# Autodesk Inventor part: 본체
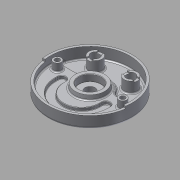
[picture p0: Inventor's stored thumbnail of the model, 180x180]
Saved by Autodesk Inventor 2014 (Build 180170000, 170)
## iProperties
Created: 2015-06
Part Number: 본체
Material: 알루미늄 6061
Document SubType Name: Modeling
Designer: MYHOME
Mass: 1070.49 g
Surface Area: 1035.62 cm^2
Volume: 395.014 cm^3
Density: 2.71 g/cm^3
Appearance: 알루미늄 - 평지
Author: MYHOME
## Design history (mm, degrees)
sketch "스케치1"
  geometry: C1 r 95 at (0, 0); 1 further point
  constraints: 1 centre point, 1 coincident
  dimensions: "d0" = 190 diameter of C1
extrude "돌출1" new body sketch "스케치1" distance "d1" = 32; taper "d2" = 0 deg
sketch "스케치3"
  geometry: L1 (-34.013, 24.639)-(-125.605, 24.639); L2 (34.013, 24.639)-(121.919, 24.639); C1 r 95 at (0, 0) reference; C2 r 90 at (0, 0); A1 r 42 centre (0, 0) between (-34.013, 24.639) and (34.013, 24.639)
  constraints: 4 end point, 2 centre point, 2 coincident, 2 point on circle, 1 collinear, 1 horizontal, 1 point on line
  dimensions: "d6" = 180 diameter of C2; "d125" = 84 diameter of A1; "d126" = 24.63947 distance from line of C1.centre L1
extrude "돌출3" cut sketch "스케치3" distance "d7" = 25; taper "d8" = 0 deg
sketch "스케치5"
  geometry: L1 (0, 0)-(-95, 0); L2 (0, 0)-(95, 0); L3 (0, 0)-(-94.075, -13.221); L4 (0, 0)-(94.075, -13.221); A1 r 95 centre (0, 0) between (-95, 0) and (95, 0) reference
  constraints: 8 end point, 4 point on circle, 1 collinear, 1 horizontal
  dimensions: "d12" = 8 deg angle of L3 L1; "d13" = 8 deg angle of L4 L2
extrude "돌출5" cut sketch "스케치5" distance "d14" = 5; taper "d15" = 0 deg
sketch "스케치11"
  geometry: L1 (-31.129, 16)-(-75.657, 16); L2 (31.129, 16)-(75.657, 16); A1 r 90 centre (0, 0) between (85.114, 29.25) and (-85.114, 29.25) reference; A2 r 35 centre (0, 0) between (31.129, 16) and (-31.129, 16); A3 r 10 centre (-75.657, 26) between (-85.114, 29.25) and (-75.657, 16); A4 r 10 centre (75.657, 26) between (75.657, 16) and (85.114, 29.25)
  constraints: 8 point on circle, 4 end point, 4 tangent, 3 centre point, 1 coincident, 1 collinear, 1 horizontal
  dimensions: "d36" = 70 diameter of A2; "d37" = 16 distance from line of A2.centre L1; "d38" = 16 distance from line of A1.centre L2; "d39" = 10 radius of A3; "d40" = 10 radius of A4
extrude "돌출13" join sketch "스케치11" distance "d56" = 7; taper "d57" = 0 deg
sketch "스케치14"
  geometry: C1 r 35 at (0, 0); A1 r 90 centre (0, 0) between (-85.114, 29.25) and (85.114, 29.25) reference
  constraints: 1 centre point, 1 coincident
  dimensions: "d58" = 70 diameter of C1
extrude "돌출14" join sketch "스케치14" distance "d59" = 10; taper "d60" = -10 deg
sketch "스케치15"
  geometry: L1 (75.657, 16)-(31.129, 16) reference; L2 (-50, -19)-(-50, -14); L3 (50, -19)-(50, -14); L4 (41, -14)-(41, -19); L5 (59, -14)-(59, -19); L6 (-59, -14)-(-59, -19); L7 (-41, -14)-(-41, -19); A1 r 35 centre (0, 0) between (-31.129, 16) and (31.129, 16) reference; A2 r 50 centre (0, -19) between (-50, -19) and (50, -19); A3 r 59 centre (0, -19) between (-59, -19) and (59, -19); A4 r 41 centre (0, -19) between (-41, -19) and (41, -19); A5 r 9 centre (-50, -19) between (-41, -19) and (-59, -19); A6 r 9 centre (50, -19) between (59, -19) and (41, -19); A7 r 9 centre (-50, -14) between (-59, -14) and (-41, -14); A8 r 9 centre (50, -14) between (41, -14) and (59, -14)
  constraints: 14 point on circle, 12 end point, 10 tangent, 7 centre point, 2 coincident, 2 horizontal alignment, 1 parallel, 1 perpendicular, 1 vertical alignment
  dimensions: "d61" = 19 distance of A1.centre A2.centre; "d62" = 41 radius of A4; "d63" = 59 radius of A3; "d85" = 5 distance of L2.start L2.end; "d86" = 5 distance of L3.start L3.end; "d87" = 18 diameter of A7; "d88" = 18 diameter of A8
sketch "스케치16"
  geometry: C1 r 15 at (-40, 52); C2 r 15 at (40, 52); A1 r 35 centre (0, 0) between (31.129, 16) and (-31.129, 16) reference
  constraints: 2 centre point, 1 horizontal alignment
  dimensions: "d64" = 30 diameter of C1; "d65" = 30 diameter of C2; "d66" = 52 vertical distance of A1.centre C2.centre; "d67" = 80 distance of C2.centre C1.centre; "d68" = 40 horizontal distance of A1.centre C1.centre
extrude "돌출15" join sketch "스케치16" distance "d69" = 25; taper "d70" = 0 deg
sketch "스케치17"
  geometry: C1 r 15 at (0, 0) reference; C2 r 15 at (80, 0) reference; C3 r 10 at (0, 0); C4 r 10 at (80, 0); 1 further point
  constraints: 2 centre point, 2 coincident
  dimensions: "d71" = 20 diameter of C3; "d72" = 20 diameter of C4
extrude "돌출16" cut sketch "스케치17" stored distance "d73" = 4.57143; taper "d74" = 0 deg
sketch "스케치18"
  geometry: L1 (6, -18.685)-(-6, -18.685); L2 (-6, -18.685)-(-6, 18.685); L3 (-6, 18.685)-(6, 18.685); L4 (6, 18.685)-(6, -18.685); L5 (6, -18.685)-(-6, 18.685); L6 (-6, -18.685)-(6, 18.685); C1 r 15 at (0, 0) reference; 1 further point
  constraints: 12 end point, 2 midpoint, 2 parallel, 1 horizontal, 1 perpendicular
  dimensions: "d76" = 12 distance of L2.end L3.end; "d77" = 37.37003 distance of L3.end L1.start
extrude "돌출17" cut sketch "스케치18" distance "d78" = 3; taper "d79" = 0 deg
sketch "스케치19"
  geometry: L1 (-22.578, 6)-(22.578, 6); L2 (22.578, 6)-(22.578, -6); L3 (22.578, -6)-(-22.578, -6); L4 (-22.578, -6)-(-22.578, 6); L5 (-22.578, 6)-(22.578, -6); L6 (22.578, 6)-(-22.578, -6); C1 r 10 at (0, 0) reference; 3 further points
  constraints: 12 end point, 3 midpoint, 2 parallel, 1 coincident, 1 horizontal, 1 perpendicular
  dimensions: "d81" = 12 distance between parallel lines of L3 L1; "d82" = 45.1561 distance of L1.start L1.end
extrude "돌출18" cut sketch "스케치19" distance "d83" = 3; taper "d84" = 0 deg
extrude "돌출19" cut sketch "스케치15" distance "d89" = 7; taper "d90" = 0 deg
sketch "스케치20"
  geometry: C1 r 33.237 at (0, 0) reference; C2 r 25 at (0, 0)
  constraints: 1 centre point, 1 coincident
  dimensions: "d91" = 50 diameter of C2
extrude "돌출20" cut sketch "스케치20" distance "d92" = 15; taper "d93" = 0 deg
sketch "스케치21"
  geometry: C1 r 95 at (0, 0) reference; C2 r 26 at (0, 0)
  constraints: 1 centre point, 1 coincident
  dimensions: "d94" = 52 diameter of C2
extrude "돌출21" join sketch "스케치21" distance "d95" = 12; taper "d96" = -15 deg
sketch "스케치22"
  geometry: C1 r 22.785 at (0, 0) reference; C2 r 11.5 at (0, 0)
  constraints: 1 centre point, 1 coincident
  dimensions: "d97" = 23 diameter of C2
extrude "돌출22" cut sketch "스케치22" stored distance "d98" = 12; taper "d99" = 0 deg
sketch "스케치24"
  geometry: L1 (75.657, 16)-(31.129, 16) reference; L2 (0, 0)-(74, 0); C1 r 9 at (-74, 0); C2 r 9 at (74, 0); A1 r 90 centre (0, 0) between (-85.114, 29.25) and (85.114, 29.25) reference; A2 r 74 centre (0, 0) between (-74, 0) and (74, 0)
  constraints: 3 centre point, 2 coincident, 2 end point, 2 horizontal alignment, 2 point on circle, 1 parallel
  dimensions: "d101" = 148 diameter of A2; "d102" = 18 diameter of C1; "d103" = 18 diameter of C2
extrude "돌출23" join sketch "스케치24" distance "d104" = 18; taper "d105" = 0 deg
sketch "스케치25"
  geometry: C1 r 26 at (0, 0) reference; C2 r 95 at (0, 0) reference; C3 r 9 at (-74, 0); C4 r 9 at (74, 0); A1 r 74 centre (0, 0) between (-74, 0) and (74, 0)
  constraints: 3 centre point, 3 coincident, 2 horizontal alignment, 2 point on circle
  dimensions: "d106" = 148 diameter of A1; "d107" = 18 diameter of C3; "d108" = 18 diameter of C4
extrude "돌출24" cut sketch "스케치25" distance "d109" = 11; taper "d110" = 0 deg
sketch "스케치26"
  geometry: C1 r 9 at (0, 0) reference; C2 r 9 at (-148, 0) reference; C3 r 5.5 at (0, 0); C4 r 5.5 at (-148, 0); 1 further point
  constraints: 2 centre point, 2 coincident
  dimensions: "d111" = 11 diameter of C3; "d112" = 11 diameter of C4
extrude "돌출25" cut sketch "스케치26" stored distance "d113" = 11; taper "d114" = 0 deg
sketch "스케치27"
  geometry: C1 r 95 at (0, 0) reference; C2 r 68 at (0, 0)
  constraints: 1 centre point, 1 coincident, 1 other
  dimensions: "d115" = 136 diameter of C2
feature "엠보싱1" sketch "스케치27" dims "d116" = 0.5, "d117" = 0
chamfer "모따기1" distance "d118" = 1; stored, may be unused: second distance "d119" = 2, angle "d120" = 45 deg
chamfer "모따기2" distance "d121" = 1; stored, may be unused: second distance "d122" = 2, angle "d123" = 45 deg
sketch "스케치29"
  geometry: L1 (-75.657, 16)-(-31.129, 16) reference; L2 (31.129, 16)-(75.657, 16) reference; A1 r 35 centre (0, 0) between (31.129, 16) and (-31.129, 16) reference; A2 r 90 centre (0, 0) between (85.114, 29.25) and (-85.114, 29.25) reference; A3 r 42 centre (0, 0) between (38.833, 16) and (-38.833, 16)
  constraints: 2 point on circle, 2 point on line, 1 centre point, 1 coincident
  dimensions: "d128" = 84 diameter of A3
extrude "돌출26" join sketch "스케치29" distance "d129" = 7; taper "d130" = 0 deg
fillet "모깎기2" dims "d131" = 10
fillet "모깎기4" dims "d133" = 3
fillet "모깎기5" dims "d134" = 0.3
fillet "모깎기6" dims "d135" = 3
fillet "모깎기7" dims "d136" = 5
fillet "모깎기8" dims "d137" = 1
node "솔리드1"
node "투영된 루프1"
node "투영된 루프2"
